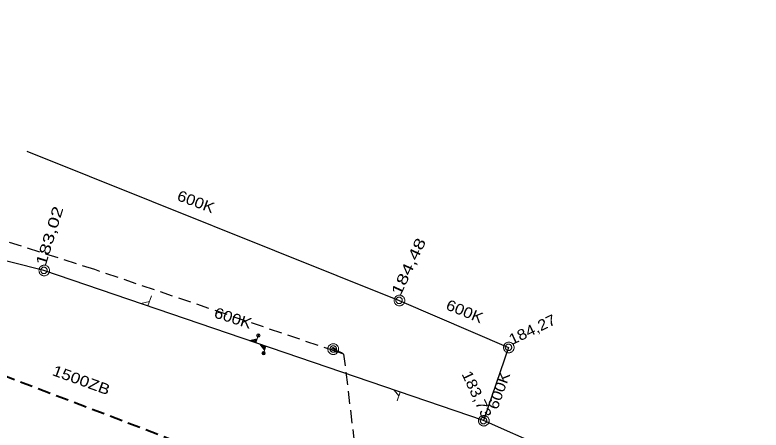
# Model space of a CAD drawing. Extents: x -740851 to -738888, y -1041382 to -1040235.
# Drawn here: x -739839.6 to -739769.6, y -1040491.1 to -1040452.2 of the extents above; entities that cross this region are included whole.
import ezdxf

# ---------------------------------------------------------------- set-up
doc = ezdxf.new("R2010")
doc.units = 0
doc.header["$LTSCALE"] = 0.4
doc.linetypes.add('MEDIUM_DASHED', pattern=[4.5, 3, -1.5])
doc.layers.add('18', color=7, linetype='Continuous', lineweight=13)
doc.layers.add('8', color=7, linetype='Continuous', lineweight=13)

msp = doc.modelspace()

# ---------------------------------------------------------------- linework, layer by layer
at = {"layer": '18', "lineweight": 25}
for p, q in [((-739838.48, -1040464.94), (-739803.58, -1040478.91)), ((-739803.58, -1040478.91), (-739793.32, -1040483.31)), ((-739793.32, -1040483.31), (-739795.67, -1040490.17)), ((-739775.87, -1040498.86), (-739795.67, -1040490.17))]:
    msp.add_line(p, q, dxfattribs=at)
msp.add_lwpolyline([(-739795.67, -1040490.17), (-739836.89, -1040476.1), (-739884.98, -1040463.99)], dxfattribs=at)
at = {"layer": '18'}
for points in [[(-739836.36, -1040476.11), (-739836.37, -1040476.06), (-739836.37, -1040476.01), (-739836.39, -1040475.96), (-739836.41, -1040475.91), (-739836.43, -1040475.86), (-739836.46, -1040475.82), (-739836.49, -1040475.78), (-739836.53, -1040475.74), (-739836.57, -1040475.71), (-739836.61, -1040475.68), (-739836.66, -1040475.66), (-739836.71, -1040475.64), (-739836.76, -1040475.62), (-739836.81, -1040475.62), (-739836.86, -1040475.61), (-739836.91, -1040475.62), (-739836.96, -1040475.62), (-739837.01, -1040475.64), (-739837.06, -1040475.66), (-739837.11, -1040475.68), (-739837.15, -1040475.71), (-739837.19, -1040475.74), (-739837.23, -1040475.78), (-739837.26, -1040475.82), (-739837.29, -1040475.86), (-739837.31, -1040475.91), (-739837.33, -1040475.96), (-739837.35, -1040476.01), (-739837.35, -1040476.06), (-739837.36, -1040476.11), (-739837.35, -1040476.16), (-739837.35, -1040476.21), (-739837.33, -1040476.26), (-739837.31, -1040476.31), (-739837.29, -1040476.36), (-739837.26, -1040476.4), (-739837.23, -1040476.44), (-739837.19, -1040476.48), (-739837.15, -1040476.51), (-739837.11, -1040476.54), (-739837.06, -1040476.56), (-739837.01, -1040476.58), (-739836.96, -1040476.6), (-739836.91, -1040476.6), (-739836.86, -1040476.61), (-739836.81, -1040476.6), (-739836.76, -1040476.6), (-739836.71, -1040476.58), (-739836.66, -1040476.56), (-739836.61, -1040476.54), (-739836.57, -1040476.51), (-739836.53, -1040476.48), (-739836.49, -1040476.44), (-739836.46, -1040476.4), (-739836.43, -1040476.36), (-739836.41, -1040476.31), (-739836.39, -1040476.26), (-739836.37, -1040476.21), (-739836.37, -1040476.16)], [(-739836.59, -1040476.1), (-739836.59, -1040476.07), (-739836.596, -1040476.04), (-739836.602, -1040476.01), (-739836.614, -1040475.98), (-739836.632, -1040475.95), (-739836.65, -1040475.926), (-739836.668, -1040475.902), (-739836.692, -1040475.878), (-739836.716, -1040475.86), (-739836.74, -1040475.842), (-739836.77, -1040475.824), (-739836.8, -1040475.812), (-739836.83, -1040475.806), (-739836.86, -1040475.8), (-739836.89, -1040475.8), (-739836.92, -1040475.8), (-739836.95, -1040475.806), (-739836.98, -1040475.812), (-739837.01, -1040475.824), (-739837.04, -1040475.842), (-739837.064, -1040475.86), (-739837.088, -1040475.878), (-739837.112, -1040475.902), (-739837.13, -1040475.926), (-739837.148, -1040475.95), (-739837.166, -1040475.98), (-739837.178, -1040476.01), (-739837.184, -1040476.04), (-739837.19, -1040476.07), (-739837.19, -1040476.1), (-739837.19, -1040476.13), (-739837.184, -1040476.16), (-739837.178, -1040476.19), (-739837.166, -1040476.22), (-739837.148, -1040476.25), (-739837.13, -1040476.274), (-739837.112, -1040476.298), (-739837.088, -1040476.322), (-739837.064, -1040476.34), (-739837.04, -1040476.358), (-739837.01, -1040476.376), (-739836.98, -1040476.388), (-739836.95, -1040476.394), (-739836.92, -1040476.4), (-739836.89, -1040476.4), (-739836.86, -1040476.4), (-739836.83, -1040476.394), (-739836.8, -1040476.388), (-739836.77, -1040476.376), (-739836.74, -1040476.358), (-739836.716, -1040476.34), (-739836.692, -1040476.322), (-739836.668, -1040476.298), (-739836.65, -1040476.274), (-739836.632, -1040476.25), (-739836.614, -1040476.22), (-739836.602, -1040476.19), (-739836.596, -1040476.16), (-739836.59, -1040476.13)], [(-739803.05, -1040478.92), (-739803.06, -1040478.87), (-739803.06, -1040478.82), (-739803.08, -1040478.77), (-739803.1, -1040478.72), (-739803.12, -1040478.67), (-739803.15, -1040478.63), (-739803.18, -1040478.59), (-739803.22, -1040478.55), (-739803.26, -1040478.52), (-739803.3, -1040478.49), (-739803.35, -1040478.47), (-739803.4, -1040478.45), (-739803.45, -1040478.43), (-739803.5, -1040478.43), (-739803.55, -1040478.42), (-739803.6, -1040478.43), (-739803.65, -1040478.43), (-739803.7, -1040478.45), (-739803.75, -1040478.47), (-739803.8, -1040478.49), (-739803.84, -1040478.52), (-739803.88, -1040478.55), (-739803.92, -1040478.59), (-739803.95, -1040478.63), (-739803.98, -1040478.67), (-739804, -1040478.72), (-739804.02, -1040478.77), (-739804.04, -1040478.82), (-739804.04, -1040478.87), (-739804.05, -1040478.92), (-739804.04, -1040478.97), (-739804.04, -1040479.02), (-739804.02, -1040479.07), (-739804, -1040479.12), (-739803.98, -1040479.17), (-739803.95, -1040479.21), (-739803.92, -1040479.25), (-739803.88, -1040479.29), (-739803.84, -1040479.32), (-739803.8, -1040479.35), (-739803.75, -1040479.37), (-739803.7, -1040479.39), (-739803.65, -1040479.41), (-739803.6, -1040479.41), (-739803.55, -1040479.42), (-739803.5, -1040479.41), (-739803.45, -1040479.41), (-739803.4, -1040479.39), (-739803.35, -1040479.37), (-739803.3, -1040479.35), (-739803.26, -1040479.32), (-739803.22, -1040479.29), (-739803.18, -1040479.25), (-739803.15, -1040479.21), (-739803.12, -1040479.17), (-739803.1, -1040479.12), (-739803.08, -1040479.07), (-739803.06, -1040479.02), (-739803.06, -1040478.97)], [(-739803.28, -1040478.91), (-739803.28, -1040478.88), (-739803.286, -1040478.85), (-739803.292, -1040478.82), (-739803.304, -1040478.79), (-739803.322, -1040478.76), (-739803.34, -1040478.736), (-739803.358, -1040478.712), (-739803.382, -1040478.688), (-739803.406, -1040478.67), (-739803.43, -1040478.652), (-739803.46, -1040478.634), (-739803.49, -1040478.622), (-739803.52, -1040478.616), (-739803.55, -1040478.61), (-739803.58, -1040478.61), (-739803.61, -1040478.61), (-739803.64, -1040478.616), (-739803.67, -1040478.622), (-739803.7, -1040478.634), (-739803.73, -1040478.652), (-739803.754, -1040478.67), (-739803.778, -1040478.688), (-739803.802, -1040478.712), (-739803.82, -1040478.736), (-739803.838, -1040478.76), (-739803.856, -1040478.79), (-739803.868, -1040478.82), (-739803.874, -1040478.85), (-739803.88, -1040478.88), (-739803.88, -1040478.91), (-739803.88, -1040478.94), (-739803.874, -1040478.97), (-739803.868, -1040479), (-739803.856, -1040479.03), (-739803.838, -1040479.06), (-739803.82, -1040479.084), (-739803.802, -1040479.108), (-739803.778, -1040479.132), (-739803.754, -1040479.15), (-739803.73, -1040479.168), (-739803.7, -1040479.186), (-739803.67, -1040479.198), (-739803.64, -1040479.204), (-739803.61, -1040479.21), (-739803.58, -1040479.21), (-739803.55, -1040479.21), (-739803.52, -1040479.204), (-739803.49, -1040479.198), (-739803.46, -1040479.186), (-739803.43, -1040479.168), (-739803.406, -1040479.15), (-739803.382, -1040479.132), (-739803.358, -1040479.108), (-739803.34, -1040479.084), (-739803.322, -1040479.06), (-739803.304, -1040479.03), (-739803.292, -1040479), (-739803.286, -1040478.97), (-739803.28, -1040478.94)], [(-739792.79, -1040483.32), (-739792.8, -1040483.27), (-739792.8, -1040483.22), (-739792.82, -1040483.17), (-739792.84, -1040483.12), (-739792.86, -1040483.07), (-739792.89, -1040483.03), (-739792.92, -1040482.99), (-739792.96, -1040482.95), (-739793, -1040482.92), (-739793.04, -1040482.89), (-739793.09, -1040482.87), (-739793.14, -1040482.85), (-739793.19, -1040482.83), (-739793.24, -1040482.83), (-739793.29, -1040482.82), (-739793.34, -1040482.83), (-739793.39, -1040482.83), (-739793.44, -1040482.85), (-739793.49, -1040482.87), (-739793.54, -1040482.89), (-739793.58, -1040482.92), (-739793.62, -1040482.95), (-739793.66, -1040482.99), (-739793.69, -1040483.03), (-739793.72, -1040483.07), (-739793.74, -1040483.12), (-739793.76, -1040483.17), (-739793.78, -1040483.22), (-739793.78, -1040483.27), (-739793.79, -1040483.32), (-739793.78, -1040483.37), (-739793.78, -1040483.42), (-739793.76, -1040483.47), (-739793.74, -1040483.52), (-739793.72, -1040483.57), (-739793.69, -1040483.61), (-739793.66, -1040483.65), (-739793.62, -1040483.69), (-739793.58, -1040483.72), (-739793.54, -1040483.75), (-739793.49, -1040483.77), (-739793.44, -1040483.79), (-739793.39, -1040483.81), (-739793.34, -1040483.81), (-739793.29, -1040483.82), (-739793.24, -1040483.81), (-739793.19, -1040483.81), (-739793.14, -1040483.79), (-739793.09, -1040483.77), (-739793.04, -1040483.75), (-739793, -1040483.72), (-739792.96, -1040483.69), (-739792.92, -1040483.65), (-739792.89, -1040483.61), (-739792.86, -1040483.57), (-739792.84, -1040483.52), (-739792.82, -1040483.47), (-739792.8, -1040483.42), (-739792.8, -1040483.37)], [(-739793.02, -1040483.31), (-739793.02, -1040483.28), (-739793.026, -1040483.25), (-739793.032, -1040483.22), (-739793.044, -1040483.19), (-739793.062, -1040483.16), (-739793.08, -1040483.136), (-739793.098, -1040483.112), (-739793.122, -1040483.088), (-739793.146, -1040483.07), (-739793.17, -1040483.052), (-739793.2, -1040483.034), (-739793.23, -1040483.022), (-739793.26, -1040483.016), (-739793.29, -1040483.01), (-739793.32, -1040483.01), (-739793.35, -1040483.01), (-739793.38, -1040483.016), (-739793.41, -1040483.022), (-739793.44, -1040483.034), (-739793.47, -1040483.052), (-739793.494, -1040483.07), (-739793.518, -1040483.088), (-739793.542, -1040483.112), (-739793.56, -1040483.136), (-739793.578, -1040483.16), (-739793.596, -1040483.19), (-739793.608, -1040483.22), (-739793.614, -1040483.25), (-739793.62, -1040483.28), (-739793.62, -1040483.31), (-739793.62, -1040483.34), (-739793.614, -1040483.37), (-739793.608, -1040483.4), (-739793.596, -1040483.43), (-739793.578, -1040483.46), (-739793.56, -1040483.484), (-739793.542, -1040483.508), (-739793.518, -1040483.532), (-739793.494, -1040483.55), (-739793.47, -1040483.568), (-739793.44, -1040483.586), (-739793.41, -1040483.598), (-739793.38, -1040483.604), (-739793.35, -1040483.61), (-739793.32, -1040483.61), (-739793.29, -1040483.61), (-739793.26, -1040483.604), (-739793.23, -1040483.598), (-739793.2, -1040483.586), (-739793.17, -1040483.568), (-739793.146, -1040483.55), (-739793.122, -1040483.532), (-739793.098, -1040483.508), (-739793.08, -1040483.484), (-739793.062, -1040483.46), (-739793.044, -1040483.43), (-739793.032, -1040483.4), (-739793.026, -1040483.37), (-739793.02, -1040483.34)], [(-739795.14, -1040490.18), (-739795.15, -1040490.13), (-739795.15, -1040490.08), (-739795.17, -1040490.03), (-739795.19, -1040489.98), (-739795.21, -1040489.93), (-739795.24, -1040489.89), (-739795.27, -1040489.85), (-739795.31, -1040489.81), (-739795.35, -1040489.78), (-739795.39, -1040489.75), (-739795.44, -1040489.73), (-739795.49, -1040489.71), (-739795.54, -1040489.69), (-739795.59, -1040489.69), (-739795.64, -1040489.68), (-739795.69, -1040489.69), (-739795.74, -1040489.69), (-739795.79, -1040489.71), (-739795.84, -1040489.73), (-739795.89, -1040489.75), (-739795.93, -1040489.78), (-739795.97, -1040489.81), (-739796.01, -1040489.85), (-739796.04, -1040489.89), (-739796.07, -1040489.93), (-739796.09, -1040489.98), (-739796.11, -1040490.03), (-739796.13, -1040490.08), (-739796.13, -1040490.13), (-739796.14, -1040490.18), (-739796.13, -1040490.23), (-739796.13, -1040490.28), (-739796.11, -1040490.33), (-739796.09, -1040490.38), (-739796.07, -1040490.43), (-739796.04, -1040490.47), (-739796.01, -1040490.51), (-739795.97, -1040490.55), (-739795.93, -1040490.58), (-739795.89, -1040490.61), (-739795.84, -1040490.63), (-739795.79, -1040490.65), (-739795.74, -1040490.67), (-739795.69, -1040490.67), (-739795.64, -1040490.68), (-739795.59, -1040490.67), (-739795.54, -1040490.67), (-739795.49, -1040490.65), (-739795.44, -1040490.63), (-739795.39, -1040490.61), (-739795.35, -1040490.58), (-739795.31, -1040490.55), (-739795.27, -1040490.51), (-739795.24, -1040490.47), (-739795.21, -1040490.43), (-739795.19, -1040490.38), (-739795.17, -1040490.33), (-739795.15, -1040490.28), (-739795.15, -1040490.23)], [(-739795.37, -1040490.17), (-739795.37, -1040490.14), (-739795.376, -1040490.11), (-739795.382, -1040490.08), (-739795.394, -1040490.05), (-739795.412, -1040490.02), (-739795.43, -1040489.996), (-739795.448, -1040489.972), (-739795.472, -1040489.948), (-739795.496, -1040489.93), (-739795.52, -1040489.912), (-739795.55, -1040489.894), (-739795.58, -1040489.882), (-739795.61, -1040489.876), (-739795.64, -1040489.87), (-739795.67, -1040489.87), (-739795.7, -1040489.87), (-739795.73, -1040489.876), (-739795.76, -1040489.882), (-739795.79, -1040489.894), (-739795.82, -1040489.912), (-739795.844, -1040489.93), (-739795.868, -1040489.948), (-739795.892, -1040489.972), (-739795.91, -1040489.996), (-739795.928, -1040490.02), (-739795.946, -1040490.05), (-739795.958, -1040490.08), (-739795.964, -1040490.11), (-739795.97, -1040490.14), (-739795.97, -1040490.17), (-739795.97, -1040490.2), (-739795.964, -1040490.23), (-739795.958, -1040490.26), (-739795.946, -1040490.29), (-739795.928, -1040490.32), (-739795.91, -1040490.344), (-739795.892, -1040490.368), (-739795.868, -1040490.392), (-739795.844, -1040490.41), (-739795.82, -1040490.428), (-739795.79, -1040490.446), (-739795.76, -1040490.458), (-739795.73, -1040490.464), (-739795.7, -1040490.47), (-739795.67, -1040490.47), (-739795.64, -1040490.47), (-739795.61, -1040490.464), (-739795.58, -1040490.458), (-739795.55, -1040490.446), (-739795.52, -1040490.428), (-739795.496, -1040490.41), (-739795.472, -1040490.392), (-739795.448, -1040490.368), (-739795.43, -1040490.344), (-739795.412, -1040490.32), (-739795.394, -1040490.29), (-739795.382, -1040490.26), (-739795.376, -1040490.23), (-739795.37, -1040490.2)]]:
    msp.add_lwpolyline(points, close=True, dxfattribs=at)
at = {"layer": '18', "linetype": 'MEDIUM_DASHED', "lineweight": 40}
msp.add_lwpolyline([(-739801.38, -1040504.08), (-739824.522, -1040492.113), (-739843.173, -1040485.007), (-739862.094, -1040478.655), (-739868.01, -1040476.84)], dxfattribs=at)
at = {"layer": '18'}
for points in [[(-739826.814, -1040478.478), (-739827.138, -1040479.426), (-739827.814, -1040479.195), (-739826.992, -1040478.999)], [(-739816.729, -1040482.042), (-739817.015, -1040482.882), (-739817.615, -1040482.677), (-739816.886, -1040482.503)], [(-739816.959, -1040482.572), (-739817.042, -1040482.817), (-739817.425, -1040482.686), (-739816.955, -1040482.573)], [(-739817.033, -1040482.645), (-739817.075, -1040482.767), (-739817.271, -1040482.7), (-739817.029, -1040482.647)], [(-739816.343, -1040484.001), (-739816.072, -1040483.206), (-739816.639, -1040483.012), (-739816.194, -1040483.565)], [(-739816.209, -1040483.471), (-739816.13, -1040483.239), (-739816.492, -1040483.116), (-739816.205, -1040483.472)], [(-739816.222, -1040483.373), (-739816.183, -1040483.257), (-739816.369, -1040483.194), (-739816.218, -1040483.374)], [(-739803.761, -1040488.306), (-739803.486, -1040487.502), (-739804.06, -1040487.306), (-739803.61, -1040487.865)]]:
    msp.add_lwpolyline(points, dxfattribs=at)
for centre, radius in [((-739816.782, -1040482.196), 0.167), ((-739816.782, -1040482.195), 0.0826), ((-739816.294, -1040483.856), 0.158), ((-739816.295, -1040483.858), 0.0782)]:
    msp.add_circle(centre, radius, dxfattribs=at)
at = {"layer": '8'}
for p, q in [((-739808.9, -1040483.822), (-739809.9, -1040483.43)), ((-739809.529, -1040483.761), (-739809.429, -1040483.661)), ((-739809.529, -1040483.661), (-739809.429, -1040483.761)), ((-739809.529, -1040483.661), (-739809.529, -1040483.681)), ((-739809.529, -1040483.661), (-739809.509, -1040483.661)), ((-739809.529, -1040483.761), (-739809.529, -1040483.741)), ((-739809.529, -1040483.761), (-739809.509, -1040483.761)), ((-739809.429, -1040483.661), (-739809.449, -1040483.661)), ((-739809.429, -1040483.761), (-739809.449, -1040483.761)), ((-739809.429, -1040483.661), (-739809.429, -1040483.681)), ((-739809.429, -1040483.761), (-739809.429, -1040483.741))]:
    msp.add_line(p, q, dxfattribs=at)
at = {"layer": '8', "lineweight": 25}
msp.add_line((-739809.48, -1040483.712), (-739809.44, -1040483.61), dxfattribs=at)
at = {"layer": '8', "linetype": 'MEDIUM_DASHED', "lineweight": 25}
for points in [[(-739809.48, -1040483.712), (-739832.13, -1040476.03), (-739840.77, -1040473.27), (-739864.43, -1040466.88), (-739898.28, -1040460.1), (-739963.421, -1040452.173)], [(-739769.636, -1040515.065), (-739798.96, -1040501.6), (-739806.89, -1040499.33), (-739808.75, -1040483.96), (-739809.48, -1040483.712)]]:
    msp.add_lwpolyline(points, dxfattribs=at)
at = {"layer": '8'}
for points in [[(-739809.255, -1040483.47), (-739809.255, -1040483.425), (-739809.255, -1040483.364), (-739809.27, -1040483.318), (-739809.285, -1040483.258), (-739809.315, -1040483.212), (-739809.346, -1040483.167), (-739809.376, -1040483.137), (-739809.422, -1040483.091), (-739809.452, -1040483.061), (-739809.497, -1040483.031), (-739809.543, -1040483), (-739809.603, -1040482.985), (-739809.649, -1040482.97), (-739809.709, -1040482.97), (-739809.755, -1040482.97), (-739809.815, -1040482.97), (-739809.861, -1040482.97), (-739809.906, -1040482.985), (-739809.967, -1040483), (-739810.012, -1040483.031), (-739810.058, -1040483.061), (-739810.088, -1040483.091), (-739810.134, -1040483.137), (-739810.164, -1040483.167), (-739810.194, -1040483.212), (-739810.225, -1040483.258), (-739810.24, -1040483.318), (-739810.255, -1040483.364), (-739810.255, -1040483.425), (-739810.255, -1040483.47), (-739810.255, -1040483.531), (-739810.255, -1040483.576), (-739810.24, -1040483.622), (-739810.225, -1040483.682), (-739810.194, -1040483.728), (-739810.164, -1040483.773), (-739810.134, -1040483.803), (-739810.088, -1040483.849), (-739810.058, -1040483.879), (-739810.012, -1040483.909), (-739809.967, -1040483.94), (-739809.906, -1040483.955), (-739809.861, -1040483.97), (-739809.815, -1040483.97), (-739809.755, -1040483.97), (-739809.709, -1040483.97), (-739809.649, -1040483.97), (-739809.603, -1040483.955), (-739809.543, -1040483.94), (-739809.497, -1040483.909), (-739809.452, -1040483.879), (-739809.422, -1040483.849), (-739809.376, -1040483.803), (-739809.346, -1040483.773), (-739809.315, -1040483.728), (-739809.285, -1040483.682), (-739809.27, -1040483.622), (-739809.255, -1040483.576), (-739809.255, -1040483.531)], [(-739809.452, -1040483.47), (-739809.452, -1040483.44), (-739809.467, -1040483.409), (-739809.467, -1040483.379), (-739809.482, -1040483.349), (-739809.497, -1040483.318), (-739809.512, -1040483.288), (-739809.528, -1040483.273), (-739809.558, -1040483.243), (-739809.573, -1040483.228), (-739809.603, -1040483.212), (-739809.634, -1040483.197), (-739809.664, -1040483.182), (-739809.694, -1040483.182), (-739809.725, -1040483.167), (-739809.755, -1040483.167), (-739809.785, -1040483.167), (-739809.815, -1040483.182), (-739809.846, -1040483.182), (-739809.876, -1040483.197), (-739809.906, -1040483.212), (-739809.937, -1040483.228), (-739809.952, -1040483.243), (-739809.982, -1040483.273), (-739809.997, -1040483.288), (-739810.012, -1040483.318), (-739810.028, -1040483.349), (-739810.043, -1040483.379), (-739810.043, -1040483.409), (-739810.058, -1040483.44), (-739810.058, -1040483.47), (-739810.058, -1040483.5), (-739810.043, -1040483.531), (-739810.043, -1040483.561), (-739810.028, -1040483.591), (-739810.012, -1040483.622), (-739809.997, -1040483.652), (-739809.982, -1040483.667), (-739809.952, -1040483.697), (-739809.937, -1040483.712), (-739809.906, -1040483.728), (-739809.876, -1040483.743), (-739809.846, -1040483.758), (-739809.815, -1040483.758), (-739809.785, -1040483.773), (-739809.755, -1040483.773), (-739809.725, -1040483.773), (-739809.694, -1040483.758), (-739809.664, -1040483.758), (-739809.634, -1040483.743), (-739809.603, -1040483.728), (-739809.573, -1040483.712), (-739809.558, -1040483.697), (-739809.528, -1040483.667), (-739809.512, -1040483.652), (-739809.497, -1040483.622), (-739809.482, -1040483.591), (-739809.467, -1040483.561), (-739809.467, -1040483.531), (-739809.452, -1040483.5)], [(-739809.618, -1040483.47), (-739809.618, -1040483.455), (-739809.634, -1040483.44), (-739809.634, -1040483.425), (-739809.634, -1040483.409), (-739809.649, -1040483.409), (-739809.649, -1040483.394), (-739809.664, -1040483.379), (-739809.679, -1040483.364), (-739809.694, -1040483.364), (-739809.694, -1040483.349), (-739809.709, -1040483.349), (-739809.725, -1040483.349), (-739809.74, -1040483.334), (-739809.755, -1040483.334), (-739809.77, -1040483.334), (-739809.785, -1040483.349), (-739809.8, -1040483.349), (-739809.815, -1040483.349), (-739809.815, -1040483.364), (-739809.831, -1040483.364), (-739809.846, -1040483.379), (-739809.861, -1040483.394), (-739809.876, -1040483.409), (-739809.876, -1040483.425), (-739809.876, -1040483.44), (-739809.891, -1040483.455), (-739809.891, -1040483.47), (-739809.891, -1040483.485), (-739809.876, -1040483.5), (-739809.876, -1040483.515), (-739809.876, -1040483.531), (-739809.861, -1040483.546), (-739809.846, -1040483.561), (-739809.831, -1040483.576), (-739809.815, -1040483.591), (-739809.8, -1040483.591), (-739809.785, -1040483.591), (-739809.77, -1040483.606), (-739809.755, -1040483.606), (-739809.74, -1040483.606), (-739809.725, -1040483.591), (-739809.709, -1040483.591), (-739809.694, -1040483.591), (-739809.679, -1040483.576), (-739809.664, -1040483.561), (-739809.649, -1040483.546), (-739809.649, -1040483.531), (-739809.634, -1040483.531), (-739809.634, -1040483.515), (-739809.634, -1040483.5), (-739809.618, -1040483.485)], [(-739809.429, -1040483.711), (-739809.429, -1040483.706), (-739809.43, -1040483.701), (-739809.431, -1040483.696), (-739809.433, -1040483.691), (-739809.436, -1040483.686), (-739809.439, -1040483.682), (-739809.442, -1040483.678), (-739809.446, -1040483.674), (-739809.45, -1040483.671), (-739809.454, -1040483.668), (-739809.459, -1040483.665), (-739809.464, -1040483.663), (-739809.469, -1040483.662), (-739809.474, -1040483.661), (-739809.479, -1040483.661), (-739809.484, -1040483.661), (-739809.489, -1040483.662), (-739809.494, -1040483.663), (-739809.499, -1040483.665), (-739809.504, -1040483.668), (-739809.508, -1040483.671), (-739809.512, -1040483.674), (-739809.516, -1040483.678), (-739809.519, -1040483.682), (-739809.522, -1040483.686), (-739809.525, -1040483.691), (-739809.527, -1040483.696), (-739809.528, -1040483.701), (-739809.529, -1040483.706), (-739809.529, -1040483.711), (-739809.529, -1040483.716), (-739809.528, -1040483.721), (-739809.527, -1040483.726), (-739809.525, -1040483.731), (-739809.522, -1040483.736), (-739809.519, -1040483.74), (-739809.516, -1040483.744), (-739809.512, -1040483.748), (-739809.508, -1040483.751), (-739809.504, -1040483.754), (-739809.499, -1040483.757), (-739809.494, -1040483.759), (-739809.489, -1040483.76), (-739809.484, -1040483.761), (-739809.479, -1040483.761), (-739809.474, -1040483.761), (-739809.469, -1040483.76), (-739809.464, -1040483.759), (-739809.459, -1040483.757), (-739809.454, -1040483.754), (-739809.45, -1040483.751), (-739809.446, -1040483.748), (-739809.442, -1040483.744), (-739809.439, -1040483.74), (-739809.436, -1040483.736), (-739809.433, -1040483.731), (-739809.431, -1040483.726), (-739809.43, -1040483.721), (-739809.429, -1040483.716)]]:
    msp.add_lwpolyline(points, close=True, dxfattribs=at)
at = {"layer": '8', "lineweight": 25}
msp.add_lwpolyline([(-739809.44, -1040483.61), (-739809.41, -1040483.509), (-739809.737, -1040483.406), (-739809.77, -1040483.5)], dxfattribs=at)

# ---------------------------------------------------------------- texts
at = {"layer": '18'}
for s, rotation, width, p in [('600K', 339.407, 1.15, (-739824.492, -1040469.499)), ('183,02', 72.87, 1.4, (-739836.738, -1040475.752)), ('184,48', 64.774, 1.4, (-739803.465, -1040478.55)), ('600K', 337.795, 1.15, (-739799.28, -1040479.716)), ('600K', 342.193, 1.15, (-739821.014, -1040480.487)), ('184,27', 25.565, 1.15, (-739793, -1040483.103)), ('1500ZB', 340.143, 1.2, (-739836.195, -1040485.891)), ('183,73', 295.025, 1.15, (-739797.739, -1040485.796)), ('600K', 70.162, 1.15, (-739794.363, -1040489.208))]:
    msp.add_text(s, height=1, rotation=rotation, dxfattribs=dict(at, width=width)).set_placement(p)

doc.saveas('drawing.dxf')
